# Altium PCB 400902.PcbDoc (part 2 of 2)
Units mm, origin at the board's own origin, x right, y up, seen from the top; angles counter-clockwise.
Board outline 45.72 x 50.8 mm, 4 copper layers (Top Layer, Mid-Layer 1, Mid-Layer 2, Bottom Layer), stack 1.564 mm thick; 61 components, 50 nets, 204 pads, 509 vias.
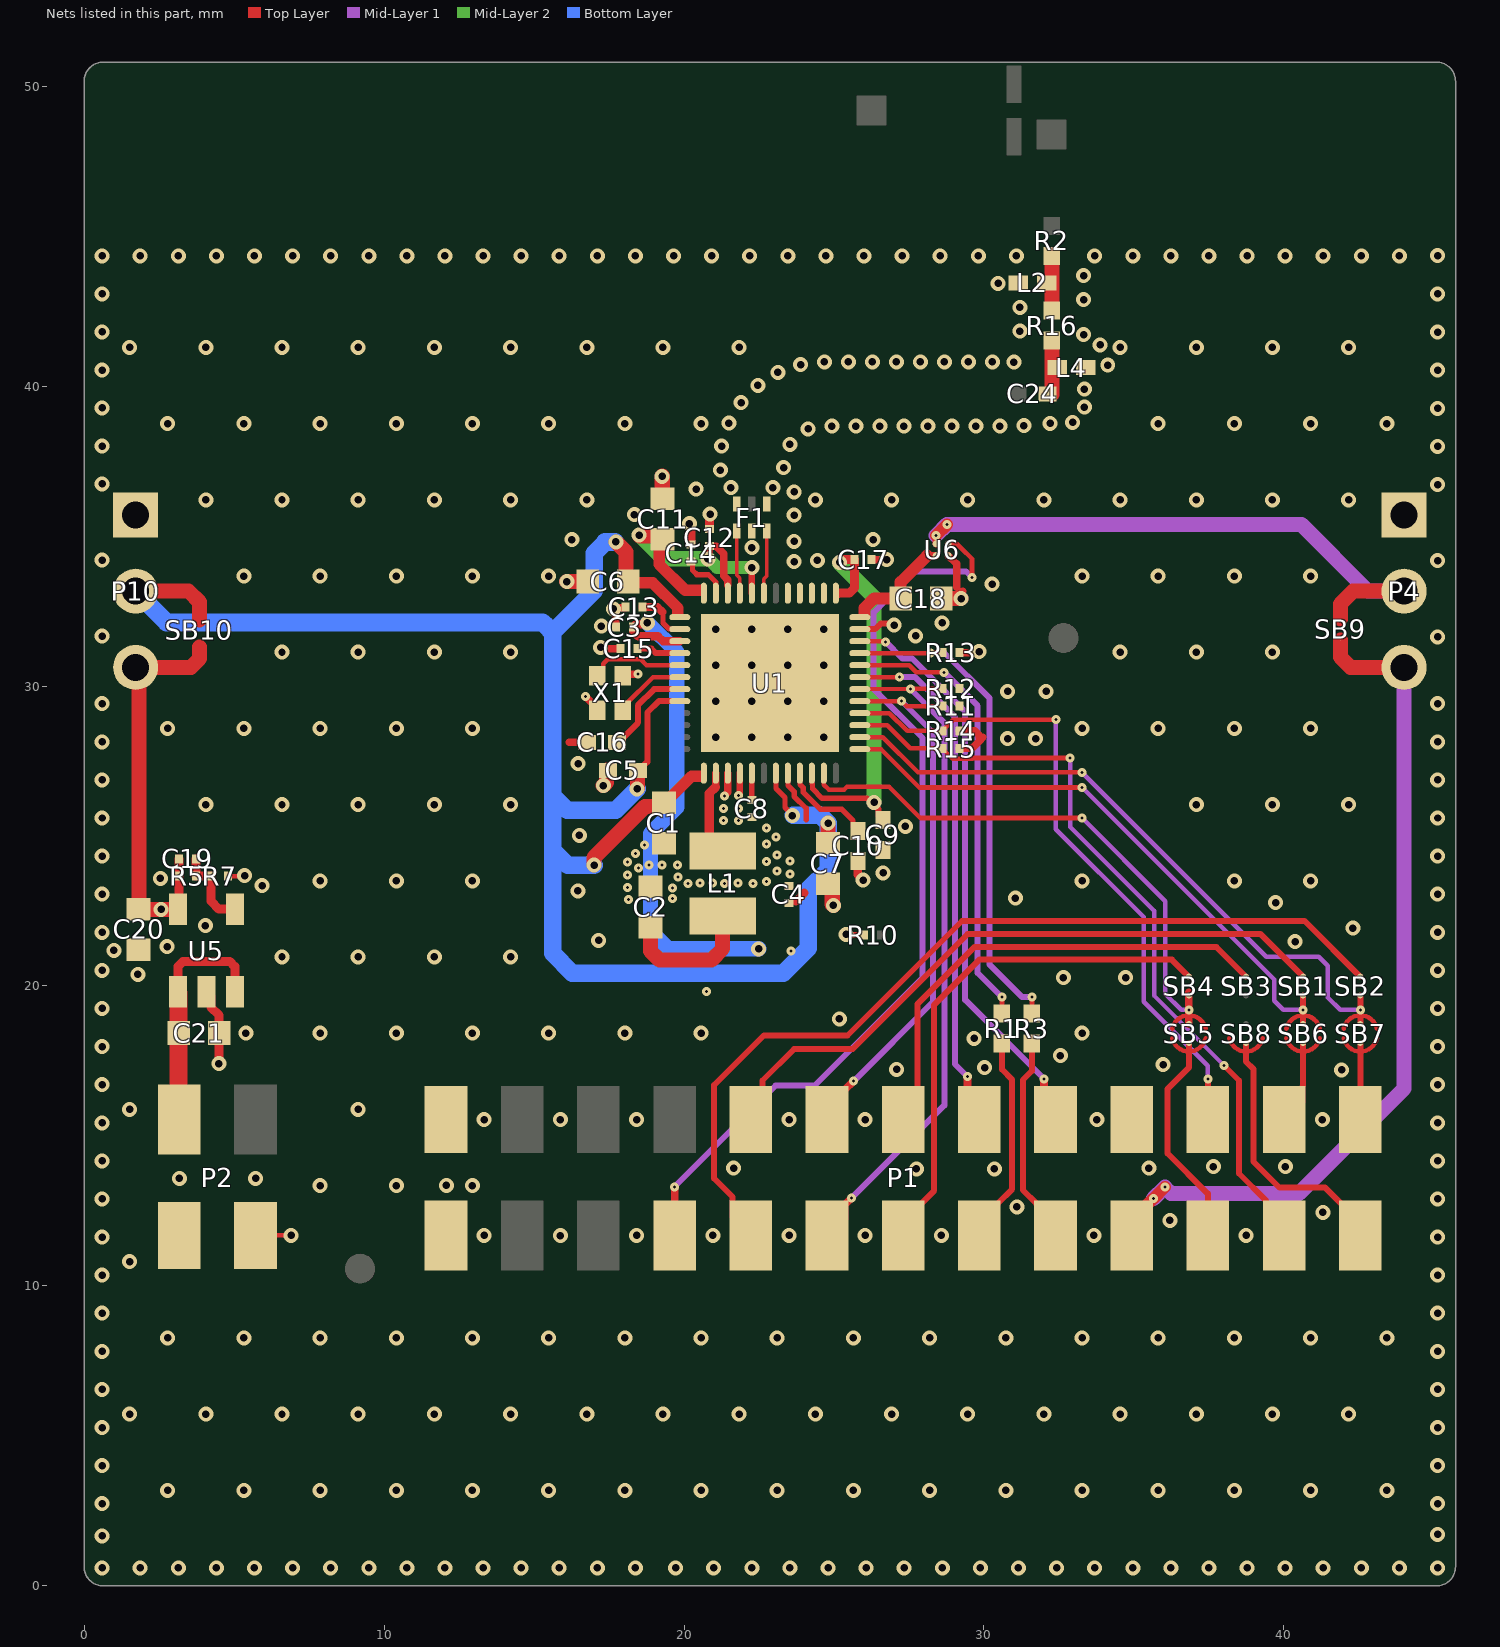
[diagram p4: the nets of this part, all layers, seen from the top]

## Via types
v1: diameter 0.5, hole 0.25, Top Layer to Bottom Layer, tented both sides, 439 vias
v2: diameter 0.3, hole 0.1, Top Layer to Mid-Layer 1, tented both sides, 70 vias

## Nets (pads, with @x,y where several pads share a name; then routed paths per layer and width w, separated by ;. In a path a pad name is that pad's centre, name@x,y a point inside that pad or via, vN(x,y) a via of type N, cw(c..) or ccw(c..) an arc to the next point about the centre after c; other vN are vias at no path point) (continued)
GND: C1.1 C2.1 C3.1 C4.1 C5.1 C6.1 C7.2 C8.2 C9.1 C10.2 C11.1 C12.2 C13.1 C14.1 C15.1 C16.1 C17.1 C18.1 C20.1 C21.1 F1.2 F1.5 F1.7 L2.1 L4.1 P1.2 P1.19 P2.2 P2.4 P4.1 P10.1 R7.1 R10.2 R11.2 R12.2 R13.1 R14.2 R15.2 U1.2 U1.3 U1.4 U1.5 U1.27 U1.28 U1.47 U1.49 U5.2 U6.B1 X1.2 X1.4 | length 21.3
  Top Layer w0.15: P2.4@5.715,11.684 v1(6.905,11.684)
  Top Layer w0.152: R7.1@4.803,23.665 5.343,23.665 v1@5.368,23.69
  Top Layer w0.2: v1(25.403,21.719) 25.415,21.706 25.988,21.706 R10.2@26.001,21.694 ; U1.47@25.86,31.895 26.371,31.895 26.553,32.076 26.959,32.076 v1(27.008,32.027)
  Top Layer w0.229: v2(21.82,26.355) 21.83,26.355 21.86,26.385 U1.28@21.86,27.095
  Top Layer w0.25: 16.18,28.121 C16.1@16.643,28.121 ; v2(16.719,29.65) 16.719,29.642 17.106,29.255 X1.2@17.156,29.255 ; C3.1@17.733,31.959 17.723,31.969 17.723,32.428 17.644,32.508 v1(17.644,32.575) 17.669,32.601 18.036,32.601 18.046,32.611 C13.1@18.046,32.626 ; X1.4@17.964,30.397 v2(18.46,30.397) ; v2(21.355,26.336) 21.355,26.349 21.46,26.454 U1.27@21.46,27.095 ; C10.2@25.794,24.167 25.781,24.153 25.781,23.713 ; C10.2@25.812,24.271 25.812,23.744 25.781,23.713 ; v1(25.969,23.525) 25.781,23.713 ; C17.1@26.256,34.217 v1(26.753,34.217) ; U6.B1@28.808,34.344 29.084,34.068 29.084,33.3 ; R15.2@29.179,27.925 29.609,27.925 29.89,28.206 29.89,28.254 29.845,28.299 ; R14.2@29.179,28.503 29.688,28.503 29.787,28.405 ; v1(29.235,32.917) 29.283,32.965 29.283,33.142 v1@29.297,33.155 ; R13.1@29.243,31.114 29.805,31.114 v1(29.837,31.145) ; 29.787,28.405 29.893,28.299 29.96,28.299
  Top Layer w0.254: v1(17.221,31.292) 17.268,31.245 C15.1@17.877,31.245
  Top Layer w0.3: U5.2@4.075,19.8 4.225,19.65 4.225,19.291 4.5,19.016 4.5,17.422 v1(4.493,17.415)
  Top Layer w0.305: v1(20.181,35.411) 20.181,35.358 20.23,35.31 20.23,34.78 C14.1@20.232,34.778 ; C12.2@20.848,35.274 20.848,35.713 v1(20.868,35.733)
  Top Layer w0.508: v1(16.092,33.481) C6.1@16.786,33.481 ; v1(17.311,26.683) 17.416,26.788 17.416,27.187 17.42,27.191 C5.1@17.462,27.191 ; v1(19.272,36.991) 19.272,36.252 C11.1@19.285,36.238 ; C7.2@24.796,23.408 24.821,23.408 24.942,23.287 24.942,22.727 v1(24.983,22.686) ; C18.1@28.573,32.917 v1(29.235,32.917)
  other v1: 0.6,0.6 1.87,0.6 3.14,0.6 4.41,0.6 5.68,0.6 6.95,0.6 8.22,0.6 9.49,0.6 10.76,0.6 12.03,0.6 13.3,0.6 14.57,0.6 15.84,0.6 17.11,0.6 18.38,0.6 19.72,0.6 20.99,0.6 22.26,0.6 23.53,0.6 24.8,0.6 26.07,0.6 27.34,0.6 28.61,0.6 29.88,0.6 31.15,0.6 32.42,0.6 33.69,0.6 34.96,0.6 36.23,0.6 37.5,0.6 38.77,0.6 40.04,0.6 41.31,0.6 42.58,0.6 43.85,0.6 45.12,0.6 0.6,1.67 45.12,1.72 0.6,2.74 45.12,2.74 2.788,3.187 5.328,3.187 7.868,3.187 10.408,3.187 12.948,3.187 15.488,3.187 18.028,3.187 20.568,3.187 23.108,3.187 25.648,3.187 28.188,3.187 30.728,3.187 33.268,3.187 35.808,3.187 38.348,3.187 40.888,3.187 43.428,3.187 0.6,4.01 45.12,4.01 0.6,5.28 45.12,5.28 1.518,5.727 4.058,5.727 6.598,5.727 9.138,5.727 11.678,5.727 14.218,5.727 16.758,5.727 19.298,5.727 21.838,5.727 24.378,5.727 26.918,5.727 29.458,5.727 31.998,5.727 34.538,5.727 37.078,5.727 39.618,5.727 42.158,5.727 0.6,6.55 45.12,6.55 0.6,7.82 45.12,7.82 2.788,8.267 5.328,8.267 7.868,8.267 10.408,8.267 12.948,8.267 15.488,8.267 18.028,8.267 20.568,8.267 23.108,8.267 25.648,8.267 28.188,8.267 30.728,8.267 33.268,8.267 35.808,8.267 38.348,8.267 40.888,8.267 43.428,8.267 0.6,9.09 45.12,9.09 0.6,10.36 45.12,10.36 1.518,10.807 0.6,11.63 45.12,11.63 15.875,11.675 13.34,11.684 18.42,11.684 20.96,11.684 23.5,11.684 26.04,11.684 28.58,11.684 33.66,11.684 38.74,11.684 36.2,12.184 41.3,12.45 31.095,12.634 0.6,12.9 45.12,12.9 7.868,13.347 10.408,13.347 12.075,13.35 12.948,13.347 3.175,13.584 5.715,13.584 27.75,13.9 30.35,13.9 21.65,13.925 35.5,13.925 37.65,13.975 40.05,13.975 0.6,14.17 45.12,14.17 0.6,15.44 45.12,15.44 13.34,15.545 15.88,15.545 18.42,15.545 23.5,15.545 26.04,15.545 33.76,15.545 41.28,15.545 1.518,15.887 9.138,15.887 0.6,16.71 45.12,16.71 27.088,17.219 41.925,17.2 30.025,17.275 35.975,17.375 32.55,17.675 0.6,17.98 45.12,17.98 29.675,18.25 5.393,18.427 7.868,18.427 10.408,18.427 12.948,18.427 15.488,18.427 18.028,18.427 20.568,18.427 33.268,18.427 25.175,18.9 0.6,19.25 45.12,19.25 32.65,20.275 34.725,20.275 1.795,20.385 0.6,20.52 45.12,20.52 6.598,20.967 9.138,20.967 11.678,20.967 14.218,20.967 0.993,21.19 2.768,21.315 40.375,21.475 17.156,21.517 0.6,21.79 45.12,21.79 42.3,21.925 4.043,22.015 39.725,22.775 31.05,22.925 0.6,23.06 45.12,23.06 16.462,23.167 5.933,23.347 7.868,23.507 10.408,23.507 12.948,23.507 33.268,23.507 38.348,23.507 40.888,23.507 2.543,23.59 5.355,23.677 26.641,23.769 0.6,24.33 45.12,24.33 16.513,25.021 27.381,25.323 0.6,25.6 45.12,25.6 4.058,26.047 6.598,26.047 9.138,26.047 11.678,26.047 14.218,26.047 37.078,26.047 39.618,26.047 42.158,26.047 0.6,26.87 45.12,26.87 16.47,27.415 0.6,28.14 45.12,28.14 30.784,28.249 31.725,28.25 21.06,28.295 22.26,28.295 23.46,28.295 24.66,28.295 2.788,28.587 5.328,28.587 7.868,28.587 10.408,28.587 12.948,28.587 33.268,28.587 35.808,28.587 38.348,28.587 40.888,28.587 0.6,29.41 45.12,29.41 21.06,29.495 22.26,29.495 23.46,29.495 24.66,29.495 30.784,29.819 32.075,29.825 21.06,30.695 22.26,30.695 23.46,30.695 24.66,30.695 6.598,31.127 9.138,31.127 11.678,31.127 14.218,31.127 34.538,31.127 37.078,31.127 39.618,31.127 45.12,31.64 0.6,31.665 27.725,31.675 21.06,31.895 22.26,31.895 23.46,31.895 24.66,31.895 17.242,31.993 28.603,32.109 30.269,33.4 5.328,33.667 7.868,33.667 10.408,33.667 12.948,33.667 15.488,33.667 33.268,33.667 35.808,33.667 38.348,33.667 40.888,33.667 23.669,34.15 45.12,34.18 0.6,34.2 24.444,34.192 22.26,34.615 23.669,34.825 16.259,34.876 26.302,34.878 23.669,35.7 18.344,35.717 4.058,36.207 6.598,36.207 9.138,36.207 11.678,36.207 14.218,36.207 16.758,36.207 24.378,36.207 26.918,36.207 29.458,36.207 31.998,36.207 34.538,36.207 37.078,36.207 39.618,36.207 42.158,36.207 23.669,36.475 20.407,36.56 21.56,36.615 22.96,36.615 45.12,36.715 0.6,36.735 21.211,37.2 23.32,37.279 45.12,37.99 0.6,38 21.254,37.999 23.527,38.052 24.135,38.572 24.93,38.667 25.73,38.667 26.53,38.667 27.33,38.667 28.13,38.667 28.93,38.667 29.73,38.667 30.53,38.667 31.329,38.677 2.788,38.747 5.328,38.747 7.868,38.747 10.408,38.747 12.948,38.747 15.488,38.747 18.028,38.747 20.568,38.747 32.201,38.754 35.808,38.747 38.348,38.747 40.888,38.747 43.428,38.747 21.495,38.762 32.954,38.792 45.12,39.26 0.6,39.27 33.35,39.3 21.9,39.452 33.344,39.9 22.459,40.024 23.13,40.459 0.6,40.535 45.12,40.53 34.126,40.702 23.887,40.717 24.682,40.808 25.482,40.808 26.282,40.808 27.082,40.808 27.882,40.808 28.682,40.808 29.482,40.808 30.282,40.808 30.994,40.798 1.518,41.287 4.058,41.287 6.598,41.287 9.138,41.287 11.678,41.287 14.218,41.287 16.758,41.287 19.298,41.287 21.838,41.287 34.538,41.287 37.078,41.287 39.618,41.287 42.158,41.287 33.875,41.375 33.321,41.713 0.6,41.805 45.12,41.795 31.199,41.829 31.2,42.625 33.318,42.884 0.6,43.07 45.12,43.07 30.469,43.425 33.318,43.684 0.6,44.34 1.87,44.34 3.14,44.34 4.41,44.34 5.68,44.34 6.95,44.34 8.22,44.34 9.49,44.34 10.76,44.34 12.03,44.34 13.3,44.34 14.57,44.34 15.84,44.34 17.11,44.34 18.38,44.34 19.65,44.34 20.92,44.34 22.19,44.34 23.46,44.34 24.73,44.34 26,44.34 27.27,44.34 28.54,44.34 29.81,44.34 31.08,44.34 33.69,44.34 34.96,44.34 36.23,44.34 37.5,44.34 38.77,44.34 40.04,44.34 41.31,44.34 42.58,44.34 43.85,44.34 45.12,44.345
  other v2: 20.755,19.814 23.574,21.16 18.156,22.877 19.608,22.91 18.124,23.287 19.617,23.272 20.128,23.421 20.539,23.433 20.955,23.433 21.355,23.421 21.804,23.433 22.304,23.421 22.754,23.48 19.798,23.635 18.124,23.698 23.531,23.738 23.1,23.839 18.487,23.93 18.839,24.032 19.265,24.032 19.785,24.033 18.124,24.133 22.753,24.144 23.531,24.173 23.1,24.373 18.385,24.413 18.676,24.692 22.754,24.728 23.074,24.968 22.753,25.259 21.324,25.523 21.82,25.523 21.324,25.916 21.82,25.916
GRANT: P1.15 U1.43 | length 17.6
  Top Layer w0.152: U1.43@25.861,30.295 v2(27.191,30.295)
  Top Layer w0.254: v2(29.45,16.975) 29.45,16.34 P1.15@30.245,15.545
  Mid-Layer 1 w0.2: v2(27.191,30.295) 27.705,30.295 29.027,28.974 29.027,25.1 29.027,17.398 v2(29.45,16.975)
IOVDD_nRF70: C18.2 U1.48 U6.A1 | length 3.6
  Top Layer w0.254: 28.106,34.344 U6.A1@28.408,34.344
  Top Layer w0.4: 26.01,32.395 26.01,32.598 26.329,32.917 C18.2@27.223,32.917 27.223,33.462 28.106,34.344
IRQ: P1.17 U1.46 | length 19.5
  Top Layer w0.152: U1.46@25.86,31.495 25.869,31.485 26.709,31.485 v2(26.719,31.475)
  Top Layer w0.254: v2(32.003,16.907) 32.003,16.337 32.785,15.555 P1.17@32.785,15.545
  Mid-Layer 1 w0.2: v2(26.719,31.475) 27.277,30.918 27.606,30.918 29.243,29.281 29.375,29.149 29.375,19.534 v2(32.003,16.907)
MISO/D1: SB2.1 SB7.1 U1.38 | length 22
  Top Layer w0.152: U1.38@25.86,28.295 26.63,28.295 27.799,27.125 29.243,27.125 v2(33.275,27.125)
  Top Layer w0.2: SB7.1@42.545,18.727 42.545,19.02 v2(42.545,19.206) SB2.1@42.545,19.685
  Mid-Layer 1 w0.152: v2(33.275,27.125) 33.275,27.113 39.411,20.977 41.162,20.977 41.466,20.673 41.466,19.617 41.876,19.206 v2(42.545,19.206)
MOSI/D0: SB1.1 SB6.1 U1.37 | length 19.7
  Top Layer w0.152: U1.37@25.86,27.895 26.569,27.895 27.847,26.617 29.243,26.617 v2(33.275,26.617)
  Top Layer w0.203: SB6.1@40.64,18.727 40.64,19.02 v2(40.64,19.206) SB1.1@40.64,19.685
  Mid-Layer 1 w0.152: v2(33.275,26.617) 39.675,20.217 39.675,19.513 39.982,19.206 v2(40.64,19.206)
NetC8_1: C8.1 U1.29 | length 0.9
  Top Layer w0.191: C8.1@22.258,26.201 U1.29@22.26,27.095
  Top Layer w0.254: C8.1@22.258,26.201 C8.1@22.266,26.193
NetC10_1: C10.1 U1.33 | length 3.2
  Top Layer w0.178: U1.33@23.86,27.095 23.864,27.09 23.864,26.718 23.976,26.606 23.976,26.451 24.532,25.895 25.256,25.895 25.633,25.518 25.633,25.328 C10.1@25.794,25.167
NetC13_2: C13.2 U1.14 | length 1.7
  Top Layer w0.178: 19.28,32.465 19.299,32.446 19.299,32.102 19.502,31.899 19.856,31.899 U1.14@19.86,31.895
  Top Layer w0.267: C13.2@18.616,32.626 19.119,32.626 19.28,32.465
NetC15_2: C15.2 U1.16 | length 1.5
  Top Layer w0.203: C15.2@18.447,31.245 18.907,31.245 19.045,31.107 19.072,31.107 19.082,31.096 19.858,31.096 U1.16@19.86,31.095
NetC16_2: C16.2 U1.19 | length 3.2
  Top Layer w0.2: C16.2@17.77,28.121 17.82,28.121 18.446,28.747 18.446,28.767 18.459,28.78 18.459,29.258 18.462,29.261 18.462,29.353 19.003,29.895 U1.19@19.86,29.895
NetC19_2: C19.2 R5.1 R7.2 U5.4 | length 2.8
  Top Layer w0.3: C19.2@3.728,24.24 R5.1@3.728,23.665 R7.2@4.233,23.665 4.233,22.825 4.493,22.565 5.01,22.565 U5.4@5.025,22.55
NetC24_1: C24.1 L4.2 R16.2 | length 1.9
  Top Layer w0.5: C24.1@32.26,39.715 R16.2@32.26,41.565
NetL1_1: L1.1 U1.26 | length 3.4
  Top Layer w0.198: L1.1@20.841,24.954 L1.1@21.289,24.506
  Top Layer w0.254: 21.05,26.629 21.06,26.639 U1.26@21.06,27.095
  Top Layer w0.305: L1.1@20.841,24.954 20.841,26.42 21.05,26.629
  Top Layer w0.381: L1.1@21.219,24.506 L1.1@21.289,24.506
  Top Layer w0.508: L1.1@20.794,24.506 L1.1@21.219,24.506
NetL2_2: L2.2 R2.2 R16.1 | length 1.8
  Top Layer w0.5: R16.1@32.26,42.515 R2.2@32.26,44.365
NetP1_16: P1.16 R1.1 | length 7
  Top Layer w0.2: P1.16@29.845,11.684 29.845,12.144 30.455,12.754 30.466,12.754 30.942,13.229 30.942,16.879 30.6,17.221 R1.1@30.6,18.075
NetP1_18: P1.18 R3.1 | length 7
  Top Layer w0.2: R3.1@31.6,18.075 31.6,17.171 31.299,16.87 31.299,13.193 31.738,12.754 31.775,12.754 32.385,12.144 P1.18@32.385,11.684
NetP1_22: P1.22 SB5.2 | length 7.3
  Top Layer w0.2: SB5.2@36.83,18.103 36.83,17.815 36.83,17.276 36.125,16.571 36.125,14.414 37.465,13.074 P1.22@37.465,11.684
NetP1_23: P1.23 SB6.2 | length 2.8
  Top Layer w0.2: P1.23@40.005,15.545 40.615,16.155 40.615,16.657 40.64,16.682 SB6.2@40.64,18.103
NetP1_25: P1.25 SB7.2 | length 2.6
  Top Layer w0.2: P1.25@42.545,15.545 SB7.2@42.545,18.103
NetP1_26: P1.26 SB8.2 | length 8.9
  Top Layer w0.2: SB8.2@38.735,18.103 38.735,17.815 38.735,17.478 38.977,17.236 38.977,14.148 39.85,13.275 41.375,13.275 41.896,12.754 41.935,12.754 42.545,12.144 P1.26@42.545,11.684
NetP4_2: P4.2 SB9.1 U6.A2 | length 20.2
  Top Layer w0.254: U6.A2@28.408,34.744 v2(28.408,35.022)
  Top Layer w0.4: v2(28.408,35.022) v2(28.767,35.381)
  Top Layer w0.5: SB9.1@41.878,32.235 41.878,32.733 42.305,33.16 P4.2@44.003,33.16
  Mid-Layer 1 w0.5: v2(28.408,35.022) v2(28.767,35.381) 29.243,35.381 40.583,35.381 42.804,33.16 P4.2@44.003,33.16
NetU1_17: U1.17 X1.1 | length 3.4
  Top Layer w0.152: X1.1@16.945,30.458 X1.1@17.125,30.458 ; X1.1@17.114,30.346 17.114,30.458 17.176,30.458 17.313,30.595 17.313,30.742 17.461,30.89 18.553,30.89 18.748,30.695 U1.17@19.86,30.695
NetU1_18: U1.18 X1.3 | length 2.4
  Top Layer w0.152: X1.3@18.046,29.375 18.966,30.295 U1.18@19.86,30.295
  Top Layer w0.165: X1.3@17.851,29.134 X1.3@17.964,29.247
PALDO: C11.2 C12.1 U1.8 U1.10 U1.12 | length 10.6
  Top Layer w0.229: U1.8@22.26,33.095 v1@22.26,34.025
  Top Layer w0.254: v1(20.794,34.243) 20.841,34.29 20.841,34.594 C12.1@20.868,34.62 ; C12.1@20.848,34.662 20.856,34.654 21.073,34.654 21.324,34.403 21.324,33.67 21.46,33.534 U1.10@21.46,33.36
  Top Layer w0.381: C11.2@19.174,34.777 19.174,34.054 20.038,33.191 U1.12@20.57,33.191
  Top Layer w0.508: v1@18.525,35.009 19.164,35.009 C11.2@19.285,34.888 C11.2@19.174,34.777
  Mid-Layer 2 w0.432: 19.231,34.324 19.312,34.243 ; v1(20.794,34.243) 20.813,34.243 21.106,33.95 v1(22.26,33.95)
  Mid-Layer 2 w0.508: v1@18.571,34.984 19.231,34.324 ; 19.312,34.243 v1(20.794,34.243)
  other v1: 18.505,35.03
PWRIOVDD: C9.2 C17.2 U1.1 U1.34 | length 14
  Top Layer w0.178: U1.34@24.26,27.095 24.264,27.09 24.264,26.749 24.271,26.742 24.281,26.733 24.281,26.577 24.602,26.256 26.117,26.256 26.25,26.124 v1(26.337,26.124)
  Top Layer w0.203: v1(26.337,26.124) 26.337,26.043 26.482,25.898 26.482,25.686 C9.2@26.63,25.537
  Top Layer w0.305: 25.16,33.095 25.164,33.099 25.507,33.099 25.686,33.277 C17.2@25.686,34.217 25.304,34.217 25.207,34.12 v1(25.19,34.12)
  Mid-Layer 2 w0.508: v1@25.19,34.106 26.337,32.959 v1(26.337,26.124)
QSPI_D2: P1.24 R15.1 U1.39 | length 26.4
  Top Layer w0.152: U1.39@25.86,28.695 26.775,28.695 27.545,27.925 R15.1@28.609,27.925 28.609,27.91 28.668,27.851 28.683,27.851 28.934,27.6 28.942,27.6 28.965,27.577 29.243,27.577 29.622,27.577 29.645,27.6 v2(32.875,27.6)
  Top Layer w0.2: v2(38,17.35) 38.5,16.85 38.5,13.75 39.395,12.855 39.395,12.294 P1.24@40.005,11.684
  Mid-Layer 1 w0.152: v2(32.875,27.6) 32.875,25.3 35.669,22.506 35.669,19.681 v2(38,17.35)
QSPI_D3: P1.21 R14.1 U1.40 | length 22.4
  Top Layer w0.152: U1.40@25.86,29.095 26.845,29.095 27.436,28.503 R14.1@28.609,28.503 28.609,28.518 28.668,28.577 28.683,28.577 28.975,28.87 29.243,28.87 32.388,28.87 v2(32.397,28.878)
  Top Layer w0.2: v2(37.46,16.907) 37.46,15.55 P1.21@37.465,15.545
  Mid-Layer 1 w0.152: v2(32.397,28.878) 32.397,25.228 35.325,22.3 35.325,19.472 37.46,17.337 v2(37.46,16.907)
REQ: P1.12 R12.1 U1.42 | length 23.1
  Top Layer w0.14: U1.42@25.86,29.895 25.863,29.897 27.547,29.897 v2(27.55,29.9)
  Top Layer w0.152: v2(27.55,29.9) 27.555,29.905 28.604,29.905 R12.1@28.609,29.91
  Top Layer w0.254: P1.12@24.765,11.684 25.348,12.267 25.348,12.693 v2(25.58,12.925)
  Mid-Layer 1 w0.2: v2(25.58,12.925) 28.677,16.021 28.677,25.1 28.677,28.773 v2(27.55,29.9)
SCLK: SB4.1 SB5.1 U1.35 | length 18.6
  Top Layer w0.152: U1.35@24.66,27.095 24.66,26.709 24.821,26.549 25.344,26.549 25.433,26.638 26.835,26.638 27.873,25.6 29.243,25.6 v2(33.275,25.6)
  Top Layer w0.254: SB5.1@36.83,18.727 36.83,19.02 v2(36.83,19.206) SB4.1@36.83,19.685 36.83,19.785
  Mid-Layer 1 w0.152: v2(33.275,25.6) 36.047,22.828 36.047,19.735 36.575,19.206 v2(36.83,19.206)
SPI_CS: P1.13 SB3.2 | length 16.2
  Top Layer w0.2: P1.13@27.305,15.545 27.79,16.03 27.79,19.405 29.681,21.295 37.75,21.295 SB3.2@38.735,20.31
SPI_MISO: P1.10 SB2.2 | length 30.1
  Top Layer w0.2: P1.10@22.225,11.684 21.615,12.294 21.615,12.973 21,13.588 21,16.692 22.658,18.35 25.45,18.35 29.265,22.165 40.689,22.165 SB2.2@42.545,20.31
SPI_MOSI: P1.9 SB1.2 | length 22.1
  Top Layer w0.2: P1.9@22.225,15.545 22.618,15.938 22.618,16.848 23.67,17.9 25.625,17.9 29.45,21.725 39.225,21.725 SB1.2@40.64,20.31
SPI_SCLK: P1.14 SB4.2 | length 17.5
  Top Layer w0.2: P1.14@27.305,11.684 27.305,12.144 28.341,13.18 28.341,19.37 29.846,20.875 36.265,20.875 SB4.2@36.83,20.31
STAT: P1.11 R11.1 U1.41 | length 19
  Top Layer w0.152: U1.41@25.86,29.495 25.869,29.485 27.235,29.485 v2(27.25,29.5) 27.418,29.332 R11.1@28.609,29.332
  Top Layer w0.254: P1.11@24.48,15.37 24.48,15.67 25.348,16.538 25.363,16.538 v2(25.65,16.825)
  Mid-Layer 1 w0.2: v2@25.656,16.825 28.3,19.469 28.3,25.1 28.3,28.45 v2(27.25,29.5)
STATUS1: R3.2 R13.2 U1.45 | length 16.6
  Top Layer w0.152: U1.45@25.86,31.095 28.22,31.095 v2(28.225,31.1) 28.595,31.1 R13.2@28.609,31.114 ; R3.2@31.6,19.075 v2(31.6,19.625)
  Mid-Layer 1 w0.2: v2(28.225,31.1) 28.683,31.1 30.179,29.604 30.179,20.721 31.275,19.625 v2(31.6,19.625)
SW_CTRL0: R1.2 U1.44 | length 15.1
  Top Layer w0.152: U1.44@25.86,30.695 27.505,30.695 27.743,30.457 v2(28.673,30.457) ; R1.2@30.6,19.075 v2(30.6,19.625)
  Mid-Layer 1 w0.2: v2(28.673,30.457) 29.791,29.34 29.791,20.434 v2(30.6,19.625)
SXLDO: C14.2 U1.11 | length 1.6
  Top Layer w0.178: C14.2@20.224,34.14 C14.2@20.232,34.147 ; C14.2@20.247,34.147 20.28,34.114 20.28,33.861 20.428,33.712 20.807,33.712 21.06,33.459 U1.11@21.06,33.095
TXRF0: F1.1 U1.9 | length 2.1
  Top Layer w0.12: F1.1@21.76,35.165 21.76,33.698 21.86,33.598 U1.9@21.86,33.095
TXRF1: F1.3 U1.7 | length 2.1
  Top Layer w0.12: U1.7@22.66,33.095 22.66,33.566 22.76,33.666 F1.3@22.76,35.165
VBAT: C1.2 C5.2 C6.2 C7.1 P10.2 SB10.2 U1.13 U1.20 U1.25 U1.31 | length 66.7
  Top Layer w0.178: U1.31@23.06,27.095 23.064,27.09 23.064,26.587 23.367,26.284 23.367,25.948 v1@23.516,25.799
  Top Layer w0.2: C5.2@18.512,27.191 18.662,27.341 18.662,27.354 18.779,27.471 18.779,29.116 19.158,29.495 U1.20@19.86,29.495
  Top Layer w0.381: C6.2@18.136,33.481 18.284,33.481 18.32,33.445 18.953,33.445 19.798,32.6 19.798,32.395 ; C1.2@19.357,26.101 20.255,26.999 20.506,26.999
  Top Layer w0.5: P10.2@1.618,33.16 P10.2@1.718,33.16 3.485,33.16 3.845,32.8 SB10.2@3.845,32.209
  Top Layer w0.508: v1(16.999,24.032) 16.999,24.278 18.701,25.98 19.211,25.98 C1.2@19.332,26.101 ; v1(17.729,34.801) 18.066,34.465 C6.2@18.066,33.506 ; v1@18.45,26.583 C5.2@18.45,27.18 ; C7.1@24.796,24.758 24.804,24.766 v1(24.804,25.426)
  Bottom Layer w0.584: v1(16.999,24.032) 16.119,24.032 15.621,24.53 ; v1@17.628,34.801 17.378,34.801 17.373,34.797 17.006,34.429 17.006,33.175 15.621,31.79 15.621,27.176 15.621,26.343 ; v1(18.438,26.571) 17.727,25.861 16.104,25.861 15.621,26.343 ; v1@23.649,25.686 24.544,25.686 v1(24.804,25.426) 24.804,23.88 24.143,23.219 24.143,21.263 23.305,20.425 16.281,20.425 15.621,21.085 15.621,24.53 ; 15.621,24.53 15.621,26.343
  Bottom Layer w0.6: P10.2@1.718,33.16 2.753,32.125 15.286,32.125 15.374,32.037 15.621,31.79 ; 17.373,34.797 v1@17.704,34.797
  other v1: 23.61,25.682
VDD_3V6: C19.1 C20.2 P10.3 R5.2 SB10.1 U5.5 | length 13.8
  Top Layer w0.3: U5.5@3.158,22.583 C19.1@3.158,24.24
  Top Layer w0.5: U5.5@3.125,22.55 3.117,22.558 v1(2.568,22.558) 1.825,22.558 1.825,30.412 1.618,30.62 1.825,30.62 3.557,30.62 3.85,30.913 3.85,31.294
VDD_5V: C21.2 P2.1 U5.1 U5.3 | length 8.4
  Top Layer w0.2: P2.1@3.175,15.085 P2.1@3.175,15.545
  Top Layer w0.3: U5.1@3.125,19.8 3.125,20.646 3.301,20.822 4.849,20.822 5.025,20.646 U5.3@5.025,19.8 U5.3@5.035,19.79
  Top Layer w0.6: U5.1@3.15,19.763 3.15,15.57 P2.1@3.175,15.545
VDD_BUCK: C2.2 C3.2 C4.2 L1.2 U1.15 U1.32 | length 24
  Top Layer w0.178: U1.32@23.46,27.095 23.464,27.09 23.464,26.687 23.671,26.48 23.671,26.322 24.07,25.924 24.07,25.537
  Top Layer w0.279: C3.2@18.303,31.959 18.303,31.965 18.402,32.064 18.68,32.064 18.716,32.1 18.716,32.113 18.722,32.106 v1(18.782,32.106) v1@18.74,32.064 ; C3.2@18.307,31.821 18.473,31.655 19.139,31.655 19.3,31.495 U1.15@19.86,31.495 ; 23.729,22.823 24.014,23.108
  Top Layer w0.5: C2.2@18.887,21.957 18.887,21.16 19.18,20.867 20.913,20.867 21.289,21.243 L1.2@21.289,22.336
  Bottom Layer w0.508: v1(18.782,32.106) 19.761,31.127 19.761,25.959 18.885,25.083 18.885,21.837 19.485,21.238 v1(22.488,21.238) v1@22.492,21.238
VDD_IO: P1.1 P1.20 P4.3 SB9.2 | length 29
  Top Layer w0.4: P1.20@34.925,11.684 35.435,12.194 P1.20@35.435,12.604 ; P1.20@35.335,12.604 v2(35.646,12.916) ; v2@35.654,12.916 v2(36.029,13.291)
  Top Layer w0.5: SB9.2@41.878,31.535 41.878,30.967 42.225,30.62 P4.3@44.003,30.62
  Mid-Layer 1 w0.5: v2(35.646,12.916) 35.654,12.916 v2(36.029,13.291) 36.24,13.08 40.505,13.08 44.003,16.578 P4.3@44.003,30.62
VDDIOEN: P1.8 U6.B2 | length 31.2
  Top Layer w0.152: U6.B2@28.808,34.744 29.095,34.744 29.243,34.597 29.6,34.239 v2(29.6,33.625)
  Top Layer w0.254: v2(19.675,13.3) 19.675,13.288 19.685,13.278 P1.8@19.685,11.684
  Mid-Layer 1 w0.2: v2(19.675,13.3) 23.05,16.675 24.35,16.675 27.95,20.275 27.95,25.1 27.95,28.269 26.323,29.897 26.323,32.45 27.697,33.824 29.243,33.824 29.401,33.824 v2(29.6,33.625)
pads on no net: A1.1 A1.2 A1.3 Fid1.0 Fid2.0 P1.3 P1.4 P1.5 P1.6 P2.3 U1.6 U1.21 U1.22 U1.23 U1.24

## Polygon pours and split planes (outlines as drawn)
GND on Mid-Layer 1 "Mid_Layer_1-GND" (solid, remove dead copper, pour order 7): 0,0 0,50.8 45.72,50.8 45.72,0
GND on Mid-Layer 1 "Mid_Layer_1-GND_BUCK" (solid, pour order 12): 17.894,21.896 18.918,20.872 22.517,20.872 24.014,22.369 24.014,27.176 23.185,28.005 20.951,28.005 20.219,27.273 20.219,26.999 17.894,24.674
GND on Top Layer "Top_Layer-GND" (solid, remove dead copper, pour order 13): 0,0 0,50.8 45.72,50.8 45.72,0
VDD_BUCK on Top Layer "TopLayer-VDD_BUCK" (solid, pour order 11): 17.816,20.58 18.2,20.196 22.541,20.196 23.144,20.8 23.144,21.675 23.353,21.883 23.703,21.883 24.294,22.475 24.294,26.013 23.953,26.013 23.953,25.387 23.912,25.346 23.912,23.204 23.618,22.91 22.854,22.91 22.853,22.909 22.853,22.91 20.197,22.91 19.569,22.282 18.089,22.282 17.816,22.009
GND on Top Layer "Top Layer-VDD_BUCK" (solid, pour order 8): 21.324,26.624 21.324,26.556 21.16,26.392 21.16,25.44 21.274,25.327 22.484,25.327 22.515,25.297 22.515,23.738 22.448,23.673 20.142,23.673 20.001,23.814 20.001,24.9 19.604,25.297 19.068,25.297 17.96,24.189 17.96,22.767 18.095,22.632 19.593,22.632 19.74,22.779 19.74,22.783 20.117,23.16 22.555,23.16 22.555,23.15 22.629,23.077 23.604,23.077 23.755,23.228 23.755,24.423 23.581,24.597 23.406,24.597 23.234,24.768 23.234,25.432 22.85,25.816 22.075,25.816 21.984,25.907 21.984,26.624
GND on Bottom Layer "Bottom_Layer-GND" (solid, remove dead copper, pour order 6): 0,0 0,50.8 45.72,50.8 45.72,0
GND on Mid-Layer 2 "Mid_Layer_2-GND" (solid, remove dead copper, pour order 10): 0,0 0,50.8 45.72,50.8 45.72,0

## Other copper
Top Layer:
  region net GND: 19.642,25.259 20.001,24.9 20.001,23.814 20.142,23.673 22.448,23.673 22.527,23.752 22.527,25.242 22.515,25.242 22.515,25.296 22.484,25.327 21.274,25.327 21.16,25.44 21.16,26.351 21.25,26.441 21.273,26.468 21.295,26.505 21.304,26.526 21.335,26.513 21.336,26.624 21.585,26.624 21.585,26.513 21.622,26.529 21.66,26.552 21.699,26.528 21.746,26.509 21.746,26.624 21.975,26.625 21.974,26.396 21.984,26.38 21.984,25.907 22.075,25.816 22.849,25.816 22.922,25.744 22.928,25.724 22.946,25.69 22.965,25.667 22.981,25.651 22.981,25.521 22.983,25.497 22.995,25.457 23.011,25.427 23.033,25.401 23.234,25.2 23.234,24.768 23.406,24.597 23.582,24.597 23.755,24.423 23.755,23.228 23.604,23.077 22.629,23.077 22.555,23.15 22.555,23.16 20.117,23.16 19.593,22.632 18.095,22.631 17.96,22.767 17.96,24.189 19.03,25.259
  region net NetL2_2: 32.757,44.687 31.757,44.687 31.757,42.165 32.757,42.165
  region net NetC24_1: 32.76,41.865 31.76,41.865 31.76,39.314 32.76,39.314
  region net ANT: 30.785,40.238 30.785,39.238 31.46,39.238 31.46,40.238
  region net ANT: 22.641,37.041 22.385,36.395 22.385,36.065 22.135,36.065 22.135,36.395 21.879,37.041 21.879,37.311 22.641,37.311
  pour cut-out: 32.984,44.775 31.531,44.775 31.531,39.006 32.989,39.006
  pour cut-out: 21.16,35.615 23.294,35.615 23.294,33.4 21.169,33.4
  pour cut-out: 23.755,27.512 23.755,26.402 24.279,25.877 24.279,24.916 24.279,22.522 23.651,21.893 23.295,21.893 23.125,21.723 23.125,20.837 22.661,20.373 18.353,20.373 17.915,20.811 17.915,24.181 18.993,25.259 19.978,25.259 20.819,26.1 20.819,27.39 20.819,27.734 20.537,27.734 20.532,27.255 17.562,24.285 17.562,21.164 17.562,20.644 18.062,20.144 22.844,20.144 23.252,20.552 23.381,20.681 23.381,21.221 24.579,22.42 24.579,22.591 24.579,24.814 24.579,25.907 24.019,26.468 24.019,27.512
  pour cut-out: 19.978,23.012 19.724,22.758 19.724,22.66 19.952,22.66 19.978,22.686
  pour cut-out: 24.016,27.359 24.016,27.595 23.816,27.795 20.557,27.795 20.539,27.812 20.539,27.349 20.773,27.349 20.864,27.441 23.76,27.441 23.76,27.349 24.014,27.349
  pour cut-out: 17.794,22.863 18.106,22.573 20.179,22.573 20.179,22.203 18.01,22.203 17.797,21.989 17.559,21.989 17.559,22.863
  pour cut-out: 16.567,31.024 18.762,31.024 18.762,28.502 16.24,28.502 16.24,31.024
  region net ANTWIFI: 32.757,48.89 31.757,48.89 31.757,44.992 32.757,44.992
Mid-Layer 1:
  pour cut-out: 21.51,36.9 21.51,37.365 cw(c24.633,37.365) 24.633,40.488 32.227,40.488 cw(c32.227,39.738) 32.977,39.738 cw(c32.227,39.738) 32.227,38.987 24.633,38.987 ccw(c24.633,37.365) 23.011,37.365 23.011,36.9 cw(c22.26,36.9)
  pour cut-out: 43.379,19.3 36.009,19.3 36.009,20.676 43.379,20.676
  pour cut-out: 32.984,44.775 31.531,44.775 31.531,38.987 32.989,38.987
  pour cut-out: 4.545,31.184 3.178,31.184 3.178,32.409 4.545,32.409
  pour cut-out: 42.558,31.275 41.192,31.275 41.192,32.5 42.558,32.5
  pour cut-out: 20.654,28.242 20.92,27.976 20.206,27.262 20.206,27.004 17.841,24.639 17.841,21.914 18.915,20.84 22.485,20.84 24.016,22.372 24.016,27.207 24.296,27.207 24.296,22.095 22.677,20.476 18.71,20.476 17.528,21.658 17.528,24.782 19.952,27.207 19.952,27.541
  pour cut-out: 24.296,27.131 24.296,27.359 23.649,28.006 23.432,27.789 23.432,27.753 24.016,27.169 24.016,27.131
Mid-Layer 2:
  pour cut-out: 21.51,36.9 21.51,37.365 cw(c24.633,37.365) 24.633,40.488 32.227,40.488 cw(c32.227,39.738) 32.977,39.738 cw(c32.227,39.738) 32.227,38.987 24.633,38.987 ccw(c24.633,37.365) 23.011,37.365 23.011,36.9 cw(c22.26,36.9)
  pour cut-out: 32.984,44.775 31.531,44.775 31.531,38.99 32.989,38.99
Bottom Layer:
  pour cut-out: 21.51,36.9 21.51,37.365 cw(c24.633,37.365) 24.633,40.488 32.227,40.488 cw(c32.227,39.738) 32.977,39.738 cw(c32.227,39.738) 32.227,38.987 24.633,38.987 ccw(c24.633,37.365) 23.011,37.365 23.011,36.9 cw(c22.26,36.9)
  pour cut-out: 32.984,44.775 31.531,44.775 31.531,38.988 32.989,38.988
Multi-Layer:
  pour cut-out: 45.72,50.865 45.72,44.615 0,44.615 0,50.865

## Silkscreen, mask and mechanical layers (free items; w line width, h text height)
Top Overlay:
  drawing of 24 lines, arcs and shapes, not listed
  text "nRF7002-EBII" at 1.044,41.55 h2.5
  text "VBAT" at 2.626,25.1 h1.5 r90
  text "VDDIO" at 44.803,24.1 h1.5 r90
  text "SPI" at 32.25,19.275 h1.5
  text "QSPI" at 32.25,17.625 h1.5
Bottom Overlay:
  drawing of 397 lines, arcs and shapes, not listed
  text ".PCBNumber" at 44.895,49.243 h2
  text ".PCBRevision" at 44.927,48.042 h1.36
  text "GND" at 5.599,35.218 h1.6
  text "GND" at 43.024,35.218 h1.6
  text "VBAT" at 6.113,32.679 h1.6
  text "VDDIO" at 43.025,32.678 h1.6
  text "P3V6" at 5.721,30.149 h1.6
  text "VDD" at 43.025,30.139 h1.6
  text "P2" at 7.241,18.61 h2.03
  text "P1" at 43.982,18.612 h2.03
  text "GND" at 2.812,13.776 h1.6 r270
  text "GND" at 5.342,13.776 h1.6 r270
  text "GND" at 11.622,13.776 h1.6 r270
  text "N.C." at 14.136,13.775 h1.6 r270
  text "N.C." at 16.651,13.775 h1.6 r270
  text "VIOEN" at 19.24,13.775 h1.6 r270
  text "MISO" at 21.754,13.775 h1.6 r270
  text "REQ" at 24.294,13.775 h1.6 r270
  text "SCLK" at 26.883,13.775 h1.6 r270
  text "N.C." at 29.374,13.775 h1.6 r270
  text "N.C." at 31.886,13.775 h1.6 r270
  text "VDD" at 34.446,13.775 h1.6 r270
  text "Q_SCK" at 37.164,13.776 h1.6 r270
  text "Q_D2" at 39.712,13.776 h1.6 r270
  text "Q_CS" at 42.361,13.776 h1.6 r270
  text "5V0" at 2.822,9.008 h1.6 r270
  text "N.C." at 5.352,9.008 h1.6 r270
  text "VDD" at 11.622,9.008 h1.6 r270
  text "N.C." at 14.133,9.008 h1.6 r270
  text "N.C." at 16.644,9.008 h1.6 r270
  text "BCKEN" at 19.239,9.009 h1.6 r270
  text "MOSI" at 21.754,9.008 h1.6 r270
  text "STAT" at 24.294,9.008 h1.6 r270
  text "CS" at 26.863,9.009 h1.6 r270
  text "GRNT" at 29.374,9.009 h1.6 r270
  text "IRQ" at 31.886,9.008 h1.6 r270
  text "GND" at 34.446,9.009 h1.6 r270
  text "Q_D3" at 37.171,9.009 h1.6 r270
  text "Q_D0" at 39.712,9.009 h1.6 r270
  text "Q_D1" at 42.36,9.009 h1.6 r270
Top Solder:
  lines w2.2: 22.293,37.756 22.293,37.756
Board Outline:
  the board outline again, w0.152
Top Impedance Info:
  region: 32.741,41.865 31.741,41.865 31.741,39.314 32.741,39.314
  region: 32.738,44.687 31.738,44.687 31.738,42.165 32.738,42.165
  region: 30.766,40.238 30.766,39.238 31.441,39.238 31.441,40.238
  region: 22.622,37.041 22.366,36.395 22.366,36.065 22.116,36.065 22.116,36.395 21.86,37.041 21.86,37.311 22.622,37.311
  lines w0.12: 21.741,35.165 21.741,33.759 21.841,33.659 21.841,33.095 ; 22.641,33.095 22.641,33.651 22.741,33.751 22.741,35.165
  lines w1: 22.241,37.365 cw(c24.613,37.365) 24.613,39.738 30.925,39.738
  text "50 Ohm single coplanar impedance top" at 11.625,42.425 h1.2
  text "50 Ohm single impedance top-mid1" at 23.225,32.6 h1.2

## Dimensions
0,0.635 to 12.065,11.684 on Dimensions
5.715,11.684 to 12.065,11.684 on Dimensions
0,0.635 to 3.175,11.684 on Dimensions
0.636,50.8 to 0.635,0 on Dimensions
0,0.635 to 45.72,0.635 on Dimensions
